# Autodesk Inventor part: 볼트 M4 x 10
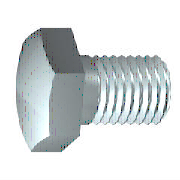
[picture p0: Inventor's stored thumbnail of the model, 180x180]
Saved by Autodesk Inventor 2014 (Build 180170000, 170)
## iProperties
Created: 2012-02
Part Number: 볼트 M4 x 10
Material: 스테인리스강
Description: 6각 머리 나사
Document SubType Name: Modeling
Standard: ISO 4017
Designer: mduedu
Standard Revision: Third edition 1999-08-15
Standards Organization: ISO
Language: ko-KR
Size Designation: M4 x 10
Categories: <MemberInstance><Categories><Category DisplayName="조임쇠" InternalName="e4da775c-781d-43d5-af7c-5136215cf5a6" Mnemonic="FSTN"><Category DisplayName="볼트" InternalN
Density: 8.08 g/cm^3
Appearance: 반광택
IsCustomPart: 0
Author: mduedu
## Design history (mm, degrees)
sketch "스케치1"
  geometry: L1 (0, 3.015)-(0, 2); L2 (2.1, 2)-(10, 2); L3 (10, 2)-(10, 0); L4 (10, 0)-(-0.4, 0); L5 (-2.48, 0)-(12.08, 0) reference; L6 (-0.4, 0)-(-0.4, 3.015); L7 (-0.4, 3.015)-(0, 3.015); L8 (2.1, 2)-(1.67, 2); L9 (1.67, 2)-(0, 2); L10 (0, -0.603)-(0, 3.618) reference
  constraints: 16 end point, 2 collinear, 2 perpendicular, 1 parallel
  dimensions: "d0" = 10 distance between parallel lines of L3 L1 (= NLG); "d1" = 7.9 distance from line of L2.start L3 (= GEL); "d2" = 4 diameter of L2 L4 (= GD); "d9" = 0.4001 distance between parallel lines of L6 L1 (computed from SD); "d10" = 6.03 diameter of L7 L4 (= SD2); "d13" = 0.42952 distance of L2.start L8.end (computed from GAL); "d14" = 4 diameter of L9 L4 (= BDM)
revolve "본체" sketch "스케치1" stored, may be unused: angle "d12" = 90 deg
sketch "스케치2"
  geometry: L1 (0, 4.041)-(3.5, 2.021); L2 (3.5, 2.021)-(3.5, -2.021); L3 (3.5, -2.021)-(0, -4.041); L4 (0, -4.041)-(-3.5, -2.021); L5 (-3.5, -2.021)-(-3.5, 2.021); L6 (-3.5, 2.021)-(0, 4.041); 2 further points
  constraints: 12 end point, 1 coincident, 1 vertical, 11 other
  dimensions: "d11" = 7 distance between parallel lines of L5 L2 (= SW)
extrude "머리" join sketch "스케치2" distance "d3" = 2.4 (= KOH - SD); taper "d4" = 0 deg
sketch "스케치4"
  geometry: L1 (-2.8, 3.5)-(-2.8, 4.041); L2 (-2.8, 4.041)-(-2.487, 4.041); L3 (-2.487, 4.041)-(-2.8, 3.5); L4 (-3.28, 0)-(0.08, 0) reference; L5 (-0.4, 4.041)-(-2.8, 4.041) reference; L6 (-2.8, 2.021)-(-2.8, 4.041) reference
  constraints: 6 end point, 2 collinear, 1 perpendicular, 1 vertical
  dimensions: "d5" = 30 deg angle of L3 L1 (= ANG1); "d19" = 7 diameter of L1.start L4 (= SW0)
revolve "모따기1" sketch "스케치4" stored, may be unused: angle "d21" = 90 deg
workplane "Work Plane1"
body "Solid1"
feature "스레드" dims "d15" = 7.9 (= GEL), "d16" = 0
chamfer "모따기2" distance "d6" = 0.42941 (= -0.5 x SPD + 0.5 x GD); stored, may be unused: second distance "d7" = 0.42952 (computed from GUL), angle "d55" = 45 deg
other parameters: "NLG" = 10 [user parameter; used in 1 equation term], "GD" = 4 (= NND) [user parameter; used in 2 equation terms], "BDM" = 4 (= NND) [user parameter; used in 1 equation term], "KOH" = 2.8 [user parameter; used in 1 equation term], "GEL" = 7.9 [user parameter; used in 2 equation terms], "SW" = 7 [user parameter; used in 2 equation terms], "SW0" = 7 (= SW) [user parameter; used in 1 equation term], "SPD" = 3.14117 (= NND - 1.2269 x PTC) [user parameter; used in 1 equation term], "SD2" = 6.03 [user parameter; used in 2 equation terms], "SD" = 0.4 [user parameter; used in 2 equation terms], "ANG1" = 30 deg [user parameter; used in 1 equation term], "GAL" = 0.42941 (= 0.61345 x PTC) [user parameter; used in 1 equation term], "GUL" = 0.42941 (= 0.61345 x PTC) [user parameter; used in 1 equation term], "d8" = 0, "RR" = 0.2 [user parameter], "d57" = 0, "d58" = 0, "TPU" = 14.28571 (computed from PTC) [user parameter], "GD1" = 3.14117 (= THREADDIA - 1.2269 x PTC) [user parameter], "THREADDIA" = 4 [user parameter; used in 1 equation term], "SDH" = 6.03 (= SD2) [user parameter], "SDHG" = 2.1 [user parameter], "TOA" = 30 deg [user parameter], "PTC" = 0.7 [user parameter; used in 5 equation terms], "NND" = 4 [user parameter; used in 3 equation terms], "E0" = 8.085 [user parameter]
